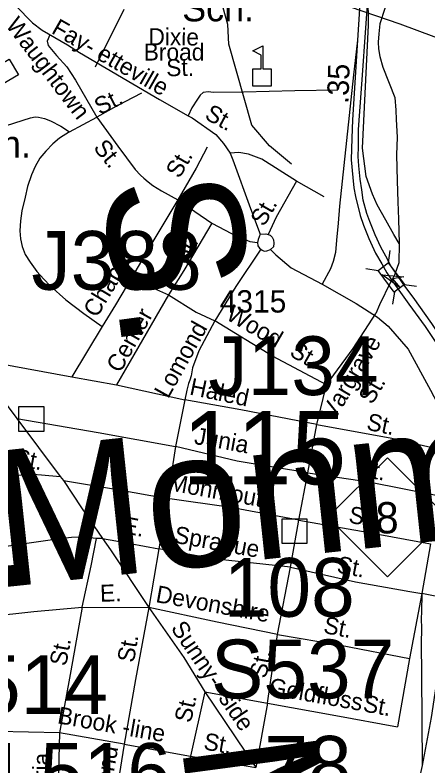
# Model space of a CAD drawing. Extents: x 1553981 to 1780076, y 812965 to 996873.
# Drawn here: x 1633766 to 1634055, y 846800 to 847325 of the extents above; entities that cross this region are included whole.
import ezdxf

# ---------------------------------------------------------------- set-up
doc = ezdxf.new("R2010")
doc.units = 0
for name, color, linetype in [('Exist Aviation Coast Guard Station CELL', 7, 'Continuous'), ('Exist Cultural Educational Facility High Label', 7, 'Continuous'), ('Exist Hydrographic Creek Single Shore', 7, 'Continuous'), ('Exist Road Non-System Structure Non-Sys Other CELL', 7, 'Continuous'), ('Exist Road Non-System Structure Non-Sys Other Number Label', 7, 'Continuous'), ('Exist Road Non-System Type 51 Label', 7, 'Continuous'), ('Exist Road Primary Interstate Structure Cantilever Sign Number Label', 7, 'Continuous'), ('Exist Road Primary Interstate Structure Ovrhead Sign Number Label', 7, 'Continuous'), ('Exist Road Primary NC Shield Number Label', 7, 'Continuous'), ('Exist Road Primary US Divided Attributed', 7, 'Continuous'), ('Exist Road Primary US Ramp 1 Lane  Attributed', 7, 'Continuous'), ('Exist Road Secondary Mileage Hundredths English Label', 7, 'Continuous'), ('Exist Road Secondary Structure Standard Bridge Attributed CELL', 7, 'Continuous'), ('Exist Road Secondary Structure Standard Bridge Number Label', 7, 'Continuous'), ('Exist Road Secondary Type 51 Attributed', 7, 'Continuous'), ('Exist Road Secondary Type 51 Number Label', 7, 'Continuous'), ('Exist Road Secondary Type 51 Undivided 4 Lane Attributed', 7, 'Continuous'), ('Exist Utilities Electrical Transmission Line', 7, 'Continuous'), ('Map Preparation Border Antique Large Shape', 7, 'Continuous'), ('Map Preparation Border County Name Lower Right Label', 7, 'Continuous'), ('Map Preparation Border Division and District Label', 7, 'Continuous'), ('Map Preparation County Base Legend CELL', 7, 'Continuous')]:
    doc.layers.add(name, color=color, linetype=linetype)

msp = doc.modelspace()

# ---------------------------------------------------------------- linework, layer by layer
at = {"layer": 'Exist Aviation Coast Guard Station CELL'}
for points in [[(1633932.23, 847274.82), (1633932.23, 847287.06), (1633937.99, 847287.06), (1633937.99, 847296.44), (1633932.11, 847299.47), (1633939.19, 847303.12), (1633939.19, 847287.06), (1633944.94, 847287.06), (1633944.94, 847274.82)], [(1633768.39, 847282.68), (1633757.78, 847276.58), (1633754.91, 847281.57), (1633746.77, 847276.89), (1633747.07, 847270.28), (1633740.38, 847274.6), (1633754.31, 847282.61), (1633751.44, 847287.6), (1633762.06, 847293.69)]]:
    msp.add_lwpolyline(points, close=True, dxfattribs=at)
at = {"layer": 'Exist Hydrographic Creek Single Shore'}
msp.add_lwpolyline([(1633959.21, 847220.5), (1633943.72, 847233.12), (1633931.47, 847247.74), (1633915.46, 847304.27), (1633914.59, 847317.83), (1633908.59, 847339.7), (1633887.22, 847381.99), (1633889.59, 847403.68), (1633897.08, 847427.75), (1633897.47, 847454.82), (1633885.22, 847477.64), (1633872.21, 847521.81), (1633858.97, 847542.59), (1633831.56, 847580.5), (1633798.8, 847599.03), (1633762.49, 847587.62), (1633733.36, 847597.48)], dxfattribs=at)
at = {"layer": 'Exist Road Non-System Structure Non-Sys Other CELL'}
for points in [[(1633768.8, 847051.22), (1633786.17, 847051.22), (1633786.17, 847033.84), (1633768.8, 847033.84)], [(1633952.55, 846972.94), (1633969.92, 846972.94), (1633969.92, 846955.55), (1633952.55, 846955.55)]]:
    msp.add_lwpolyline(points, close=True, dxfattribs=at)
at = {"layer": 'Exist Road Primary US Divided Attributed'}
for points in [[(1634008.69, 847359.68), (1634008.73, 847358.29), (1634006.57, 847328.94), (1634005.39, 847306.9)], [(1634032.18, 847144.15), (1634028.67, 847149.34), (1634024.98, 847156.29), (1634021.55, 847162.48), (1634017.62, 847171.02), (1634013.85, 847180.32), (1634011.76, 847186.09), (1634009.33, 847195.3), (1634008.31, 847202.49), (1634007.07, 847210.04), (1634006.15, 847219.25), (1634005.73, 847225.78), (1634005.9, 847232.64), (1634005.95, 847244.55), (1634008.99, 847285.72), (1634010.58, 847309.16), (1634012.68, 847338.3)], [(1634005.39, 847306.9), (1634001.71, 847251.4), (1634001.21, 847238.59), (1634000.95, 847223.34), (1634001.95, 847211.13), (1634002.63, 847203.93), (1634003.8, 847197.9), (1634007.15, 847184.67), (1634009.41, 847177.8), (1634013.1, 847168.6), (1634017.87, 847158.38), (1634022.22, 847150.85), (1634025.74, 847144.57), (1634029.42, 847139.04)], [(1634087.27, 847014.38), (1634087.44, 847025.43), (1634086.77, 847034.98), (1634085.85, 847042.51), (1634083.34, 847053.98), (1634080.66, 847063.44), (1634076.72, 847075.08), (1634071.87, 847085.63), (1634066.68, 847095.09), (1634057.3, 847109.15), (1634044.24, 847127.57), (1634037.71, 847136.28), (1634032.18, 847144.15)], [(1634029.42, 847139.04), (1634041.23, 847122.72), (1634052.44, 847107.06), (1634063.16, 847091.15), (1634068.18, 847081.78), (1634071.87, 847073.15), (1634075.3, 847063.19), (1634077.39, 847055.66), (1634079.9, 847046.61), (1634080.99, 847040.5), (1634081.91, 847032.88), (1634082.5, 847020.41)], [(1634069.1, 846916.89), (1634067.87, 846909.57), (1634062.04, 846869.79), (1634056.68, 846834.12), (1634050.39, 846800.55)], [(1634050.39, 846800.55), (1634047.41, 846787.04), (1634043.29, 846774.53)]]:
    msp.add_lwpolyline(points, dxfattribs=at)
at = {"layer": 'Exist Road Primary US Ramp 1 Lane  Attributed'}
for points in [[(1634034.3, 847165), (1634030.68, 847171.36), (1634025.07, 847181.24), (1634019.12, 847192.04), (1634015.69, 847199.4), (1634011.34, 847211.71), (1634008.75, 847231.55), (1634013.01, 847317.45), (1634012.68, 847338.3)], [(1634005.39, 847306.9), (1634002.46, 847282.88), (1633992.75, 847191.12), (1633991.83, 847179.14), (1633990.66, 847167.42), (1633989.99, 847158.72), (1633988.31, 847152.52), (1633986.47, 847147.41), (1633980.53, 847136.76)], [(1634050.16, 846920.66), (1634049.93, 846907.84), (1634049.69, 846903.18), (1634049.93, 846896.18), (1634049.69, 846885.93), (1634049.93, 846864.2), (1634050.39, 846800.55)]]:
    msp.add_lwpolyline(points, dxfattribs=at)
at = {"layer": 'Exist Road Secondary Structure Standard Bridge Attributed CELL'}
msp.add_lwpolyline([(1634034.94, 847134.28), (1634022.54, 847143.14), (1634037.71, 847141.66), (1634029.67, 847140.46)], close=True, dxfattribs=at)
at = {"layer": 'Exist Road Secondary Type 51 Attributed'}
for points in [[(1633766.61, 847330.95), (1633778.21, 847319.15), (1633785.05, 847314.06), (1633802.62, 847303.65), (1633811.08, 847298.44), (1633867.05, 847265.65), (1633887.09, 847254.1), (1633889.68, 847252.85), (1633906.4, 847241.19), (1633911.66, 847234.93), (1633916.28, 847228.15), (1633918.1, 847223.43), (1633930.53, 847189.43), (1633937.31, 847171.65)], [(1633937.31, 847171.65), (1633935.84, 847167.91), (1633935.35, 847165.75), (1633935.54, 847163.49), (1633936.82, 847161.72), (1633937.7, 847161.13), (1633938.79, 847160.34), (1633940.06, 847159.76), (1633942.03, 847159.95), (1633944.39, 847160.84)], [(1633937.31, 847171.65), (1633941.14, 847171.84), (1633942.81, 847171.35), (1633944.19, 847170.76), (1633945.76, 847169.48), (1633946.55, 847167.52), (1633946.84, 847165.16), (1633946.65, 847162.8), (1633944.39, 847160.84)], [(1633944.39, 847160.84), (1633948.12, 847157.2), (1633958.93, 847148.16), (1633980.53, 847136.76)]]:
    msp.add_lwpolyline(points, dxfattribs=at)
at = {"layer": 'Exist Road Secondary Type 51 Undivided 4 Lane Attributed'}
msp.add_lwpolyline([(1633980.53, 847136.76), (1634004.27, 847123.19), (1634019.33, 847113.64), (1634026.8, 847107.27), (1634040.61, 847091.25), (1634056.25, 847062.71), (1634065.85, 847044.58), (1634073.37, 847032.67), (1634082.5, 847020.41)], dxfattribs=at)
at = {"layer": 'Exist Utilities Electrical Transmission Line'}
msp.add_lwpolyline([(1633983.25, 847336.25), (1634034.74, 847318.32), (1634094.15, 847296.33), (1634151.37, 847277.58), (1634234.44, 847248.26), (1634301.59, 847223.9), (1634366.5, 847200.82), (1634427.91, 847178.51), (1634440.84, 847173.85), (1634492.23, 847168.2), (1634535.17, 847163.88), (1634565.08, 847160.24), (1634605.87, 847144.98), (1634663.3, 847124.23), (1634790.89, 847078.34), (1634842.13, 847060.69), (1634869.75, 847052.33), (1634976.64, 847010.96)], dxfattribs=at)
at = {"layer": 'Map Preparation Border County Name Lower Right Label'}
for p, q in [((1633842.02, 847328.42), (1633821.91, 847288.23)), ((1633803.99, 847242.99), (1633823.13, 847253.21)), ((1633981.98, 847197.52), (1633962.62, 847208.6)), ((1633873.28, 847129.14), (1633836.86, 847066.44)), ((1633826.89, 847107.16), (1633805.67, 847071.88)), ((1633737.85, 847084.58), (1633805.67, 847071.88)), ((1633805.67, 847071.88), (1633836.86, 847066.44)), ((1633836.86, 847066.44), (1633884.73, 847055.91)), ((1633976.94, 847038.74), (1633983.63, 847066.34)), ((1633755.62, 847058.45), (1633767.23, 847042.85)), ((1633884.73, 847055.91), (1633878.2, 847023.25)), ((1633767.23, 847042.85), (1633797.47, 847002.35)), ((1633970.69, 847005.02), (1633976.94, 847038.74)), ((1633878.2, 847023.25), (1633872.45, 846986.94)), ((1633964.22, 846971.99), (1633970.69, 847005.02)), ((1633797.47, 847002.35), (1633799.94, 846999.57)), ((1633872.45, 846986.94), (1633866.41, 846951.79)), ((1633958.37, 846939.04), (1633964.22, 846971.99)), ((1633827.03, 846959.15), (1633823.03, 846959.2)), ((1634056.24, 846955.29), (1634050.16, 846920.66)), ((1633866.41, 846951.79), (1633859.52, 846910.91)), ((1633949.39, 846892.21), (1633958.37, 846939.04)), ((1634050.16, 846920.66), (1634041.62, 846875.35)), ((1633813.05, 846911.11), (1633859.52, 846910.91)), ((1633942.46, 846844.12), (1633949.39, 846892.21)), ((1634041.62, 846875.35), (1634033.15, 846827.72)), ((1633898.6, 846852.06), (1633888.66, 846807.21)), ((1633898.6, 846852.06), (1633934.27, 846799.26)), ((1633898.6, 846852.06), (1633942.46, 846844.12)), ((1633942.46, 846844.12), (1633934.27, 846799.26)), ((1633797.21, 846823.38), (1633748.49, 846824.62)), ((1633797.21, 846823.38), (1633795.67, 846771.91)), ((1633842.3, 846815.44), (1633797.21, 846823.38)), ((1633842.3, 846815.44), (1633837.32, 846784.77)), ((1633842.3, 846815.44), (1633888.66, 846807.21)), ((1633888.66, 846807.21), (1633877.52, 846748.88)), ((1633888.66, 846807.21), (1633934.27, 846799.26))]:
    msp.add_line(p, q, dxfattribs=at)
for points in [[(1634028.48, 847360.69), (1634028.24, 847348.32), (1634027.59, 847338.35), (1634024.31, 847329.01), (1634020.88, 847318.37), (1634020.13, 847311.42), (1634019.71, 847305.56), (1634019.88, 847300.88), (1634020.88, 847295.6), (1634023.06, 847288.07), (1634031.24, 847267.04), (1634032.03, 847258.15), (1634032.29, 847251.6), (1634033.04, 847239.27), (1634032.54, 847226.93), (1634033.04, 847208.8), (1634033.54, 847194.2), (1634033.8, 847182.12), (1634034.3, 847165)], [(1633790.39, 847310.7), (1633788.53, 847306.38), (1633789.11, 847303.23), (1633795.01, 847296.36), (1633802.28, 847288.3), (1633808.18, 847279.16), (1633823.13, 847253.21), (1633837.8, 847233), (1633850.05, 847216.79), (1633853.75, 847212.74), (1633856.1, 847210.54), (1633859.08, 847208.08), (1633862.38, 847205.61), (1633868.31, 847201.77), (1633879.71, 847195.6), (1633903.43, 847179.25)], [(1633991.58, 847272.15), (1633961.58, 847271.63), (1633925.59, 847270.64), (1633904.68, 847270.51), (1633900.85, 847271), (1633897.41, 847270.51), (1633895.45, 847268.64), (1633893.58, 847265.89), (1633889.65, 847259.7), (1633887.09, 847254.1)], [(1633854.36, 847269.98), (1633836.99, 847261.01), (1633823.13, 847253.21)], [(1633760.13, 847247.51), (1633776.89, 847252.67), (1633780.13, 847253.36), (1633782.38, 847253.34), (1633786.69, 847252.27), (1633790.74, 847250.72), (1633798.04, 847246.84), (1633803.99, 847242.99)], [(1633803.99, 847242.99), (1633797.17, 847238.6), (1633792.36, 847234.67), (1633787.5, 847229.57), (1633783.45, 847224.58), (1633780.11, 847218.87), (1633777.54, 847212.91), (1633774.85, 847204.86), (1633773.05, 847197.47), (1633770.9, 847187.76), (1633769.78, 847180.78), (1633769.44, 847173.78), (1633769.95, 847168.32), (1633771.02, 847163.02), (1633773.18, 847157.47), (1633776.6, 847151.93), (1633781.25, 847145.6), (1633786.14, 847140.08), (1633790.6, 847135.46), (1633801.43, 847125.81), (1633814.04, 847116.1), (1633826.89, 847107.16)], [(1633900.26, 847232.28), (1633892.54, 847217.66), (1633879.71, 847195.6)], [(1633962.62, 847208.6), (1633938.37, 847223.95), (1633929.06, 847227.37), (1633922.28, 847228.64), (1633916.28, 847228.15)], [(1633962.62, 847208.6), (1633948.52, 847183.41), (1633942.81, 847171.35)], [(1633879.71, 847195.6), (1633862.29, 847166.37), (1633848.17, 847142.34)], [(1633903.43, 847179.25), (1633884.07, 847146.31), (1633873.28, 847129.14)], [(1633903.43, 847179.25), (1633917.26, 847172.05), (1633930.14, 847166.54), (1633935.35, 847165.75)], [(1634034.3, 847165), (1634034.05, 847151.66), (1634031.29, 847143.63)], [(1633937.7, 847161.13), (1633920.3, 847134.96), (1633905.7, 847110.98)], [(1633848.17, 847142.34), (1633836.13, 847122.28), (1633826.89, 847107.16)], [(1633848.17, 847142.34), (1633862.78, 847133.87), (1633873.28, 847129.14)], [(1634031.29, 847143.63), (1634029.67, 847140.46), (1634028.31, 847137.94)], [(1634028.31, 847137.94), (1634020.71, 847122.2), (1634018.12, 847116.24)], [(1633873.28, 847129.14), (1633892.5, 847117.15), (1633905.7, 847110.98)], [(1633983.63, 847066.34), (1634002.22, 847091.84), (1634018.12, 847116.24)], [(1633905.7, 847110.98), (1633894.51, 847090.12), (1633890.07, 847078.15), (1633888.99, 847072.63), (1633888.24, 847069.69), (1633887.19, 847067.21), (1633885.94, 847062.58), (1633884.73, 847055.91)], [(1633983.63, 847066.34), (1633945.95, 847086.3), (1633905.7, 847110.98)], [(1633976.94, 847038.74), (1633923.68, 847048.99), (1633884.73, 847055.91)], [(1633767.23, 847042.85), (1633824.16, 847033.05), (1633878.2, 847023.25)], [(1633976.94, 847038.74), (1634029.16, 847029.13), (1634067.51, 847020.41)], [(1633970.69, 847005.02), (1633921.33, 847013.19), (1633878.2, 847023.25)], [(1633970.69, 847005.02), (1634013.21, 846998.71), (1634062.51, 846988.88)], [(1633734.46, 846999.57), (1633762.51, 847002.63), (1633770.26, 847003.52), (1633774.27, 847003.94), (1633777.02, 847004.16), (1633778.77, 847004.13), (1633784.51, 847003.54), (1633797.47, 847002.35)], [(1633799.94, 846999.57), (1633812.39, 846980.63), (1633827.03, 846959.15)], [(1633799.94, 846999.57), (1633837.56, 846993.23), (1633872.45, 846986.94)], [(1633964.22, 846971.99), (1633916.8, 846980.77), (1633872.45, 846986.94)], [(1633964.22, 846971.99), (1634012.05, 846963.63), (1634056.24, 846955.29)], [(1633823.03, 846959.2), (1633813.57, 846960.1), (1633805.56, 846959.73), (1633795.56, 846958.64), (1633780.78, 846956.61), (1633743.45, 846951.19)], [(1633813.05, 846911.11), (1633819.24, 846940.02), (1633823.03, 846959.2)], [(1633827.03, 846959.15), (1633832.68, 846951.3), (1633859.52, 846910.91)], [(1633827.03, 846959.15), (1633836.51, 846957.5), (1633866.41, 846951.79)], [(1633958.37, 846939.04), (1633904.79, 846944.94), (1633866.41, 846951.79)], [(1633958.37, 846939.04), (1634003.8, 846928.82), (1634041.77, 846922.06), (1634050.16, 846920.66)], [(1634090.93, 846913.02), (1634085.11, 846914.18), (1634071.51, 846916.57), (1634050.16, 846920.66)], [(1633747.24, 846904.64), (1633779.27, 846908.14), (1633813.05, 846911.11)], [(1633813.05, 846911.11), (1633805.12, 846866.74), (1633797.21, 846823.38)], [(1633859.52, 846910.91), (1633850.25, 846860.8), (1633842.3, 846815.44)], [(1633859.52, 846910.91), (1633883.98, 846876.02), (1633898.6, 846852.06)], [(1633949.39, 846892.21), (1633907.34, 846900.66), (1633859.52, 846910.91)], [(1633949.39, 846892.21), (1633993.31, 846884.58), (1634041.62, 846875.35)], [(1633942.46, 846844.12), (1633990.04, 846835.65), (1634033.15, 846827.72)]]:
    msp.add_lwpolyline(points, dxfattribs=at)
at = {"layer": 'Map Preparation Border Division and District Label'}
msp.add_lwpolyline([(1633984.64, 846973.89), (1634026.27, 847015.51), (1634067.89, 846973.89), (1634026.27, 846932.26)], close=True, dxfattribs=at)
at = {"layer": 'Map Preparation County Base Legend CELL'}
for p, q in [((1634027.97, 847160.1), (1634026.72, 847151.57)), ((1634011.11, 847147.55), (1634019.64, 847146.3)), ((1634037.97, 847136.4), (1634046.5, 847135.15)), ((1634031.05, 847131.25), (1634029.8, 847122.71))]:
    msp.add_line(p, q, dxfattribs=at)
msp.add_lwpolyline([(1634026.72, 847151.57), (1634038, 847136.42), (1634030.92, 847131.15), (1634019.64, 847146.3)], close=True, dxfattribs=at)

# ---------------------------------------------------------------- texts
at = {"layer": 'Exist Cultural Educational Facility High Label'}
for s, p in [('Sch.', (1633882.81, 847320.12)), ('N.C.  Sch.', (1633662.87, 847225.04))]:
    msp.add_text(s, height=18.75, dxfattribs=at).set_placement(p)
at = {"layer": 'Exist Road Non-System Structure Non-Sys Other Number Label'}
for s, p in [('J388', (1633777.49, 847132.75)), ('J134', (1633901.1, 847059.23))]:
    msp.add_text(s, height=41.01, dxfattribs=at).set_placement(p)
at = {"layer": 'Exist Road Non-System Type 51 Label'}
for s, height, rotation, p in [('Waughtown', 11.875, 307.2914, (1633759.06, 847317.26)), ('Dixie', 11.875, 359.5592, (1633859.21, 847303.47)), ('Broad', 11.875, 0.0087, (1633855.94, 847292.77)), ('St.', 11.875, 0.9852, (1633871.75, 847281.77)), ('St.', 11.875, 27.1149, (1633825.3, 847254.43)), ('St.', 11.875, 309.1882, (1633820.28, 847231.67)), ('St.', 11.875, 59.8095, (1633880.89, 847209.86)), ('S.', 95, 277.6961, (1633825.87, 847207.22)), ('St.', 11.875, 59.9443, (1633939.99, 847176.28)), ('St.', 11.875, 60.3425, (1633885.02, 847149.68)), ('Chapel', 11.875, 59.0374, (1633823.18, 847112.65)), ('Center', 11.875, 60.7015, (1633839.52, 847074.05)), ('Wood', 11.875, 330.1105, (1633912.63, 847112.55)), ('Lomond', 11.875, 60.9015, (1633872.96, 847056.21)), ('Vargrave', 11.875, 59.2313, (1633989.25, 847040.95)), ('St.', 11.875, 330.2403, (1633957.05, 847087.05)), ('Monmouth', 95, 6.0987, (1633756.27, 846924.86)), ('Haled', 11.875, 348.1372, (1633887.41, 847059.68)), ('St.', 11.875, 59.2313, (1634015.48, 847052.05)), ('St.', 11.875, 348.1071, (1634010.99, 847035.17)), ('Junia', 11.875, 349.882, (1633890.74, 847025.18)), ('St.', 11.875, 349.6437, (1633765.07, 847010.24)), ('W.', 95, 6.0761, (1633624.11, 846910.82)), ('St.', 11.875, 349.6437, (1634004.71, 847002.95)), ('Monmouth', 11.875, 349.7647, (1633872.63, 846992.82)), ('St.', 11.875, 349.9273, (1633998.53, 846970.21)), ('E.', 11.875, 349.1878, (1633840.5, 846963)), ('Sprague', 11.875, 349.7775, (1633876.56, 846956.28)), ('St.', 11.875, 349.1311, (1633990.25, 846935.43)), ('E.', 11.875, 1.9459, (1633825.6, 846914.91)), ('Devonshire', 11.875, 349.7449, (1633863.81, 846914.79)), ('Sunny-  side', 11.875, 304.2284, (1633874.46, 846896.48)), ('St.', 11.875, 349.0456, (1633980.93, 846893.24)), ('St.', 11.875, 80.4418, (1633849.1, 846872.04)), ('St.', 11.875, 79.6624, (1633801.76, 846869.6)), ('St.', 11.875, 79.2872, (1633941.47, 846860.97)), ('Goldfloss', 11.875, 349.9055, (1633942.71, 846850.32)), ('St.', 11.875, 77.5017, (1633888.85, 846829.89)), ('St.', 11.875, 349.5777, (1634008.57, 846838.49)), ('Brook -line', 11.875, 349.9444, (1633795.12, 846830.17)), ('St.', 11.875, 350.1062, (1633897.23, 846811.96)), ('Main', 95, 277.6111, (1633882.04, 846815.83)), ('Lomond', 11.875, 80.0593, (1633828.27, 846756.77)), ('Patria', 11.875, 88.2795, (1633789.39, 846767.83))]:
    msp.add_text(s, height=height, rotation=rotation, dxfattribs=at).set_placement(p)
at = {"layer": 'Exist Road Primary Interstate Structure Cantilever Sign Number Label'}
for s, p in [('L514', (1633708.9, 846836.66)), ('L516', (1633752.93, 846775.32))]:
    msp.add_text(s, height=41.01, dxfattribs=at).set_placement(p)
at = {"layer": 'Exist Road Primary Interstate Structure Ovrhead Sign Number Label'}
msp.add_text('S537', height=41.01, dxfattribs=at).set_placement((1633902.91, 846847.52))
at = {"layer": 'Exist Road Primary NC Shield Number Label'}
msp.add_text('8', height=21.88, dxfattribs=at).set_placement((1634017.78, 846962.67))
at = {"layer": 'Exist Road Secondary Mileage Hundredths English Label'}
msp.add_text('.35', height=15, rotation=88.053, dxfattribs=at).set_placement((1633998.9, 847262.43))
at = {"layer": 'Exist Road Secondary Structure Standard Bridge Number Label'}
for s, height, p in [('115', 51.263, (1633882.99, 846996.83)), ('108', 41.01, (1633911.84, 846904.5)), ('78', 41.01, (1633940.09, 846780.29))]:
    msp.add_text(s, height=height, dxfattribs=at).set_placement(p)
at = {"layer": 'Exist Road Secondary Type 51 Number Label'}
msp.add_text('4315', height=15.625, dxfattribs=at).set_placement((1633909.06, 847116.84))
at = {"layer": 'Map Preparation Border Antique Large Shape'}
for s, rotation, p in [('Fay- etteville', 330.283, (1633790.79, 847312.22)), ('St.', 331.6708, (1633897.81, 847252.38))]:
    msp.add_text(s, height=11.875, rotation=rotation, dxfattribs=at).set_placement(p)

doc.saveas('drawing.dxf')
